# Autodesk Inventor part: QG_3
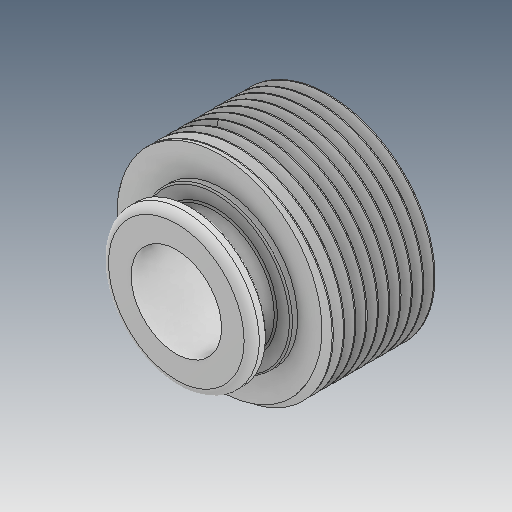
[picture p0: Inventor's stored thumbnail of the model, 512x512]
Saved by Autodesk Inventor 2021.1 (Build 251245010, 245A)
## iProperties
Created: 2021-05
Part Number: QG_3
Material: Ogólny
Document SubType Name: Modeling
Designer: user
Density: 1 g/cm^3
Appearance: Domyślna
Author: user
Revision Number: ÈÎºÎ
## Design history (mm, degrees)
feature "ÊäÈë1"
node "Bryła1"
